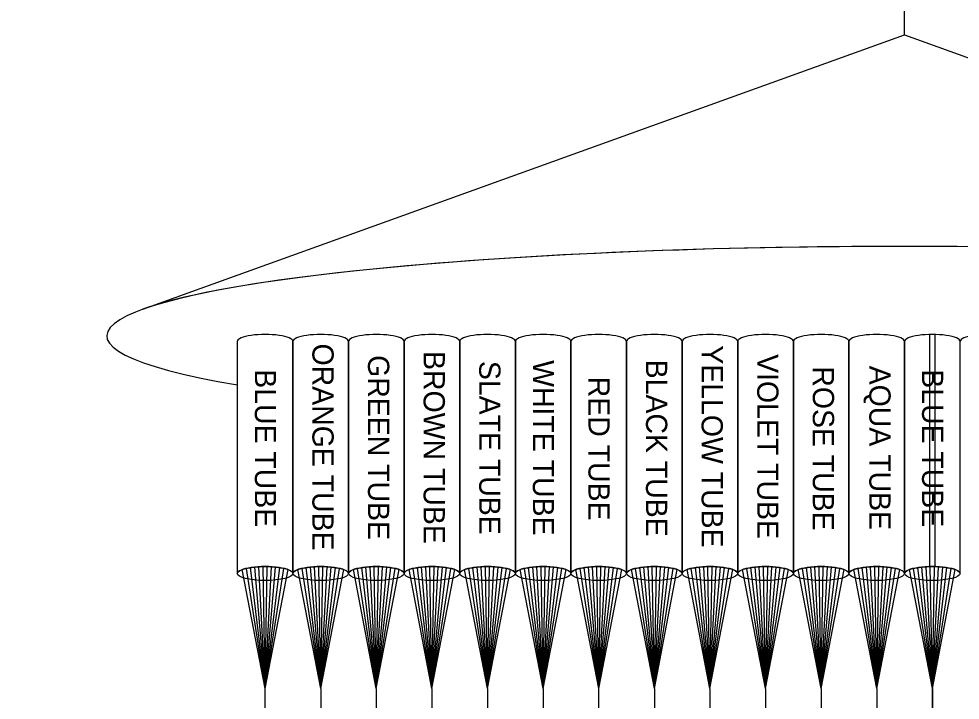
# Model space of a CAD drawing. Extents: x 1805893 to 1833564, y 708898 to 716199.
# Drawn here: x 1831726.3 to 1831827.8, y 715537.7 to 715611.3 of the extents above; entities that cross this region are included whole.
import ezdxf

# ---------------------------------------------------------------- set-up
doc = ezdxf.new("R2010")
doc.units = 0
doc.layers.add('SH_Data', color=7, linetype='Continuous')

msp = doc.modelspace()

# ---------------------------------------------------------------- linework, layer by layer
at = {"layer": 'SH_Data'}
for p, q in [((1831821.84, 715609.51), (1831821.84, 715652.24)), ((1831749.84, 715576.44), (1831749.84, 715551.39)), ((1831749.84, 715576.44), (1831749.84, 715551.39)), ((1831755.84, 715551.39), (1831755.84, 715576.44)), ((1831755.84, 715576.44), (1831755.84, 715551.39)), ((1831761.84, 715576.44), (1831761.84, 715551.39)), ((1831761.84, 715551.39), (1831761.84, 715576.44)), ((1831767.84, 715551.39), (1831767.84, 715576.44)), ((1831767.84, 715576.44), (1831767.84, 715551.39)), ((1831773.84, 715551.39), (1831773.84, 715576.44)), ((1831773.84, 715576.44), (1831773.84, 715551.39)), ((1831779.84, 715551.39), (1831779.84, 715576.44)), ((1831779.84, 715576.44), (1831779.84, 715551.39)), ((1831785.84, 715551.39), (1831785.84, 715576.44)), ((1831785.84, 715576.44), (1831785.84, 715551.39)), ((1831791.84, 715551.39), (1831791.84, 715576.44)), ((1831791.84, 715576.44), (1831791.84, 715551.39)), ((1831797.84, 715576.44), (1831797.84, 715551.39)), ((1831797.84, 715551.39), (1831797.84, 715576.44)), ((1831803.84, 715551.39), (1831803.84, 715576.44)), ((1831803.84, 715576.44), (1831803.84, 715551.39)), ((1831803.84, 715576.44), (1831803.84, 715551.39)), ((1831809.84, 715551.39), (1831809.84, 715576.44)), ((1831809.84, 715576.44), (1831809.84, 715551.39)), ((1831815.84, 715551.39), (1831815.84, 715576.44)), ((1831815.84, 715576.44), (1831815.84, 715551.39)), ((1831821.84, 715551.39), (1831821.84, 715576.44)), ((1831821.84, 715576.44), (1831821.84, 715551.39)), ((1831827.84, 715551.39), (1831827.84, 715576.44)), ((1831752.84, 715538.97), (1831752.17, 715552.12)), ((1831752.84, 715538.97), (1831752.62, 715552.14)), ((1831752.84, 715538.97), (1831753.07, 715552.14)), ((1831752.84, 715538.97), (1831753.52, 715552.12)), ((1831758.84, 715538.97), (1831758.17, 715552.12)), ((1831758.84, 715538.97), (1831758.62, 715552.14)), ((1831758.84, 715538.97), (1831759.07, 715552.14)), ((1831758.84, 715538.97), (1831759.52, 715552.12)), ((1831764.84, 715538.97), (1831764.17, 715552.12)), ((1831764.84, 715538.97), (1831764.62, 715552.14)), ((1831764.84, 715538.97), (1831765.07, 715552.14)), ((1831764.84, 715538.97), (1831765.52, 715552.12)), ((1831770.84, 715538.97), (1831770.17, 715552.12)), ((1831770.84, 715538.97), (1831770.62, 715552.14)), ((1831770.84, 715538.97), (1831771.07, 715552.14)), ((1831770.84, 715538.97), (1831771.52, 715552.12)), ((1831776.84, 715538.97), (1831776.17, 715552.12)), ((1831776.84, 715538.97), (1831776.62, 715552.14)), ((1831776.84, 715538.97), (1831777.07, 715552.14)), ((1831776.84, 715538.97), (1831777.52, 715552.12)), ((1831782.84, 715538.97), (1831782.17, 715552.12)), ((1831782.84, 715538.97), (1831782.62, 715552.14)), ((1831782.84, 715538.97), (1831783.07, 715552.14)), ((1831782.84, 715538.97), (1831783.52, 715552.12)), ((1831788.84, 715538.97), (1831788.17, 715552.12)), ((1831788.84, 715538.97), (1831788.62, 715552.14)), ((1831788.84, 715538.97), (1831789.07, 715552.14)), ((1831788.84, 715538.97), (1831789.52, 715552.12)), ((1831794.84, 715538.97), (1831794.17, 715552.12)), ((1831794.84, 715538.97), (1831794.62, 715552.14)), ((1831794.84, 715538.97), (1831795.07, 715552.14)), ((1831794.84, 715538.97), (1831795.52, 715552.12)), ((1831800.84, 715538.97), (1831800.17, 715552.12)), ((1831800.84, 715538.97), (1831800.62, 715552.14)), ((1831800.84, 715538.97), (1831801.07, 715552.14)), ((1831800.84, 715538.97), (1831801.52, 715552.12)), ((1831806.84, 715538.97), (1831806.17, 715552.12)), ((1831806.84, 715538.97), (1831806.62, 715552.14)), ((1831806.84, 715538.97), (1831807.07, 715552.14)), ((1831806.84, 715538.97), (1831807.52, 715552.12)), ((1831812.84, 715538.97), (1831812.17, 715552.12)), ((1831812.84, 715538.97), (1831812.62, 715552.14)), ((1831812.84, 715538.97), (1831813.07, 715552.14)), ((1831812.84, 715538.97), (1831813.52, 715552.12)), ((1831818.84, 715538.97), (1831818.17, 715552.12)), ((1831818.84, 715538.97), (1831818.62, 715552.14)), ((1831818.84, 715538.97), (1831819.07, 715552.14)), ((1831818.84, 715538.97), (1831819.52, 715552.12)), ((1831824.84, 715538.97), (1831824.17, 715552.12)), ((1831824.84, 715538.97), (1831824.62, 715552.14)), ((1831824.84, 715538.97), (1831825.07, 715552.14)), ((1831824.84, 715538.97), (1831825.52, 715552.12)), ((1831752.84, 715538.97), (1831750.37, 715551.81)), ((1831752.84, 715538.97), (1831750.82, 715551.94)), ((1831752.84, 715538.97), (1831751.27, 715552.03)), ((1831752.84, 715538.97), (1831751.72, 715552.08)), ((1831752.84, 715538.97), (1831753.97, 715552.08)), ((1831752.84, 715538.97), (1831754.42, 715552.03)), ((1831752.84, 715538.97), (1831754.87, 715551.94)), ((1831752.84, 715538.97), (1831755.32, 715551.81)), ((1831758.84, 715538.97), (1831756.37, 715551.81)), ((1831758.84, 715538.97), (1831756.82, 715551.94)), ((1831758.84, 715538.97), (1831757.27, 715552.03)), ((1831758.84, 715538.97), (1831757.72, 715552.08)), ((1831758.84, 715538.97), (1831759.97, 715552.08)), ((1831758.84, 715538.97), (1831760.42, 715552.03)), ((1831758.84, 715538.97), (1831760.87, 715551.94)), ((1831758.84, 715538.97), (1831761.32, 715551.81)), ((1831764.84, 715538.97), (1831762.37, 715551.81)), ((1831764.84, 715538.97), (1831762.82, 715551.94)), ((1831764.84, 715538.97), (1831763.27, 715552.03)), ((1831764.84, 715538.97), (1831763.72, 715552.08)), ((1831764.84, 715538.97), (1831765.97, 715552.08)), ((1831764.84, 715538.97), (1831766.42, 715552.03)), ((1831764.84, 715538.97), (1831766.87, 715551.94)), ((1831764.84, 715538.97), (1831767.32, 715551.81)), ((1831770.84, 715538.97), (1831768.37, 715551.81)), ((1831770.84, 715538.97), (1831768.82, 715551.94)), ((1831770.84, 715538.97), (1831769.27, 715552.03)), ((1831770.84, 715538.97), (1831769.72, 715552.08)), ((1831770.84, 715538.97), (1831771.97, 715552.08)), ((1831770.84, 715538.97), (1831772.42, 715552.03)), ((1831770.84, 715538.97), (1831772.87, 715551.94)), ((1831770.84, 715538.97), (1831773.32, 715551.81)), ((1831776.84, 715538.97), (1831774.37, 715551.81)), ((1831776.84, 715538.97), (1831774.82, 715551.94)), ((1831776.84, 715538.97), (1831775.27, 715552.03)), ((1831776.84, 715538.97), (1831775.72, 715552.08)), ((1831776.84, 715538.97), (1831777.97, 715552.08)), ((1831776.84, 715538.97), (1831778.42, 715552.03)), ((1831776.84, 715538.97), (1831778.87, 715551.94)), ((1831776.84, 715538.97), (1831779.32, 715551.81)), ((1831782.84, 715538.97), (1831780.37, 715551.81)), ((1831782.84, 715538.97), (1831780.82, 715551.94)), ((1831782.84, 715538.97), (1831781.27, 715552.03)), ((1831782.84, 715538.97), (1831781.72, 715552.08)), ((1831782.84, 715538.97), (1831783.97, 715552.08)), ((1831782.84, 715538.97), (1831784.42, 715552.03)), ((1831782.84, 715538.97), (1831784.87, 715551.94)), ((1831782.84, 715538.97), (1831785.32, 715551.81)), ((1831788.84, 715538.97), (1831786.37, 715551.81)), ((1831788.84, 715538.97), (1831786.82, 715551.94)), ((1831788.84, 715538.97), (1831787.27, 715552.03)), ((1831788.84, 715538.97), (1831787.72, 715552.08)), ((1831788.84, 715538.97), (1831789.97, 715552.08)), ((1831788.84, 715538.97), (1831790.42, 715552.03)), ((1831788.84, 715538.97), (1831790.87, 715551.94)), ((1831788.84, 715538.97), (1831791.32, 715551.81)), ((1831794.84, 715538.97), (1831792.37, 715551.81)), ((1831794.84, 715538.97), (1831792.82, 715551.94)), ((1831794.84, 715538.97), (1831793.27, 715552.03)), ((1831794.84, 715538.97), (1831793.72, 715552.08)), ((1831794.84, 715538.97), (1831795.97, 715552.08)), ((1831794.84, 715538.97), (1831796.42, 715552.03)), ((1831794.84, 715538.97), (1831796.87, 715551.94)), ((1831794.84, 715538.97), (1831797.32, 715551.81)), ((1831800.84, 715538.97), (1831798.37, 715551.81)), ((1831800.84, 715538.97), (1831798.82, 715551.94)), ((1831800.84, 715538.97), (1831799.27, 715552.03)), ((1831800.84, 715538.97), (1831799.72, 715552.08)), ((1831800.84, 715538.97), (1831801.97, 715552.08)), ((1831800.84, 715538.97), (1831802.42, 715552.03)), ((1831800.84, 715538.97), (1831802.87, 715551.94)), ((1831800.84, 715538.97), (1831803.32, 715551.81)), ((1831806.84, 715538.97), (1831804.37, 715551.81)), ((1831806.84, 715538.97), (1831804.82, 715551.94)), ((1831806.84, 715538.97), (1831805.27, 715552.03)), ((1831806.84, 715538.97), (1831805.72, 715552.08)), ((1831806.84, 715538.97), (1831807.97, 715552.08)), ((1831806.84, 715538.97), (1831808.42, 715552.03)), ((1831806.84, 715538.97), (1831808.87, 715551.94)), ((1831806.84, 715538.97), (1831809.32, 715551.81)), ((1831812.84, 715538.97), (1831810.37, 715551.81)), ((1831812.84, 715538.97), (1831810.82, 715551.94)), ((1831812.84, 715538.97), (1831811.27, 715552.03)), ((1831812.84, 715538.97), (1831811.72, 715552.08)), ((1831812.84, 715538.97), (1831813.97, 715552.08)), ((1831812.84, 715538.97), (1831814.42, 715552.03)), ((1831812.84, 715538.97), (1831814.87, 715551.94)), ((1831812.84, 715538.97), (1831815.32, 715551.81)), ((1831818.84, 715538.97), (1831816.37, 715551.81)), ((1831818.84, 715538.97), (1831816.82, 715551.94)), ((1831818.84, 715538.97), (1831817.27, 715552.03)), ((1831818.84, 715538.97), (1831817.72, 715552.08)), ((1831818.84, 715538.97), (1831819.97, 715552.08)), ((1831818.84, 715538.97), (1831820.42, 715552.03)), ((1831818.84, 715538.97), (1831820.87, 715551.94)), ((1831818.84, 715538.97), (1831821.32, 715551.81)), ((1831824.84, 715538.97), (1831822.37, 715551.81)), ((1831824.84, 715538.97), (1831822.82, 715551.94)), ((1831824.84, 715538.97), (1831823.27, 715552.03)), ((1831824.84, 715538.97), (1831823.72, 715552.08)), ((1831824.84, 715538.97), (1831825.97, 715552.08)), ((1831824.84, 715538.97), (1831826.42, 715552.03)), ((1831824.84, 715538.97), (1831826.87, 715551.94)), ((1831824.84, 715538.97), (1831827.32, 715551.81)), ((1831752.84, 715504.21), (1831752.84, 715538.97)), ((1831758.84, 715538.97), (1831758.84, 715504.21)), ((1831764.84, 715538.97), (1831764.84, 715504.21)), ((1831770.84, 715538.97), (1831770.84, 715504.21)), ((1831776.84, 715538.97), (1831776.84, 715504.21)), ((1831782.84, 715538.97), (1831782.86, 715504.21)), ((1831788.84, 715504.21), (1831788.84, 715538.97)), ((1831794.84, 715538.97), (1831794.84, 715504.21)), ((1831800.84, 715538.97), (1831800.84, 715504.21)), ((1831806.84, 715538.97), (1831806.84, 715504.21)), ((1831812.84, 715538.97), (1831812.84, 715504.21)), ((1831818.84, 715538.97), (1831818.86, 715504.21)), ((1831824.84, 715538.97), (1831824.84, 715504.21)), ((1831824.84, 715504.21), (1831824.84, 715538.97))]:
    msp.add_line(p, q, dxfattribs=at)
msp.add_lwpolyline([(1831739.65, 715579.92), (1831821.84, 715609.51), (1831904.04, 715579.92)], dxfattribs=at)
msp.add_lwpolyline([(1831739.65, 715579.92), (1831821.84, 715609.51), (1831904.04, 715579.92)], dxfattribs=at)
msp.add_lwpolyline([(1831824.54, 715577.19), (1831824.54, 715552.14), (1831825.14, 715552.14), (1831825.14, 715577.19)], close=True, dxfattribs=at)
for centre, major_axis, ratio, start_param, end_param in [((1831821.84, 715577.04), (86.09, 0), 0.112175, 5.702888, 10.005075), ((1831821.84, 715577.04), (86.09, 0), 0.112175, 5.702888, 10.005075), ((1831821.84, 715577.04), (86.09, 0), 0.112175, 0.302036, 2.839557), ((1831752.84, 715576.44), (3, 0), 0.25, 0, 3.141593), ((1831752.84, 715576.44), (3, 0), 0.25, 0, 3.141593), ((1831758.84, 715576.44), (3, 0), 0.25, 0, 3.141593), ((1831758.84, 715576.44), (3, 0), 0.25, 0, 3.141593), ((1831764.84, 715576.44), (3, 0), 0.25, 0, 3.141593), ((1831764.84, 715576.44), (3, 0), 0.25, 0, 3.141593), ((1831770.84, 715576.44), (3, 0), 0.25, 0, 3.141593), ((1831770.84, 715576.44), (3, 0), 0.25, 0, 3.141593), ((1831776.84, 715576.44), (3, 0), 0.25, 0, 3.141593), ((1831776.84, 715576.44), (3, 0), 0.25, 0, 3.141593), ((1831782.84, 715576.44), (3, 0), 0.25, 0, 3.141593), ((1831782.84, 715576.44), (3, 0), 0.25, 0, 3.141593), ((1831788.84, 715576.44), (3, 0), 0.25, 0, 3.141593), ((1831788.84, 715576.44), (3, 0), 0.25, 0, 3.141593), ((1831794.84, 715576.44), (3, 0), 0.25, 0, 3.141593), ((1831794.84, 715576.44), (3, 0), 0.25, 0, 3.141593), ((1831800.84, 715576.44), (3, 0), 0.25, 0, 3.141593), ((1831800.84, 715576.44), (3, 0), 0.25, 0, 3.141593), ((1831806.84, 715576.44), (3, 0), 0.25, 0, 3.141593), ((1831806.84, 715576.44), (3, 0), 0.25, 0, 3.141593), ((1831812.84, 715576.44), (3, 0), 0.25, 0, 3.141593), ((1831812.84, 715576.44), (3, 0), 0.25, 0, 3.141593), ((1831818.84, 715576.44), (3, 0), 0.25, 0, 3.141593), ((1831818.84, 715576.44), (3, 0), 0.25, 0, 3.141593), ((1831824.84, 715576.44), (3, 0), 0.25, 0, 3.141593), ((1831824.84, 715576.44), (3, 0), 0.25, 0, 3.141593), ((1831830.84, 715576.44), (3, 0), 0.25, 0, 3.141593), ((1831752.84, 715551.39), (3, 0), 0.25, 0, 3.141593), ((1831758.84, 715551.39), (3, 0), 0.25, 0, 3.141593), ((1831764.84, 715551.39), (3, 0), 0.25, 0, 3.141593), ((1831770.84, 715551.39), (3, 0), 0.25, 0, 3.141593), ((1831776.84, 715551.39), (3, 0), 0.25, 0, 3.141593), ((1831782.84, 715551.39), (3, 0), 0.25, 0, 3.141593), ((1831788.84, 715551.39), (3, 0), 0.25, 0, 3.141593), ((1831794.84, 715551.39), (3, 0), 0.25, 0, 3.141593), ((1831800.84, 715551.39), (3, 0), 0.25, 0, 3.141593), ((1831806.84, 715551.39), (3, 0), 0.25, 0, 3.141593), ((1831812.84, 715551.39), (3, 0), 0.25, 0, 3.141593), ((1831818.84, 715551.39), (3, 0), 0.25, 0, 3.141593), ((1831824.84, 715551.39), (3, 0), 0.25, 0, 3.141593)]:
    msp.add_ellipse(centre, major_axis=major_axis, ratio=ratio, start_param=start_param, end_param=end_param, dxfattribs=at)
for centre in [(1831752.84, 715551.39), (1831758.84, 715551.39), (1831764.84, 715551.39), (1831770.84, 715551.39), (1831776.84, 715551.39), (1831782.84, 715551.39), (1831788.84, 715551.39), (1831794.84, 715551.39), (1831800.84, 715551.39), (1831806.84, 715551.39), (1831812.84, 715551.39), (1831818.84, 715551.39), (1831824.84, 715551.39)]:
    msp.add_ellipse(centre, major_axis=(3, 0), ratio=0.25, dxfattribs=at)

# ---------------------------------------------------------------- texts
for s, height, p in [('ORANGE TUBE', 2.2947, (1831757.94, 715576.21)), ('YELLOW TUBE', 2.2947, (1831799.94, 715576.02)), ('GREEN TUBE', 2.295, (1831763.94, 715574.96)), ('BROWN TUBE', 2.295, (1831769.94, 715575.4)), ('VIOLET TUBE', 2.2947, (1831805.94, 715575.07)), ('SLATE TUBE', 2.295, (1831775.94, 715574.34)), ('WHITE TUBE', 2.295, (1831781.73, 715574.42)), ('BLACK TUBE', 2.295, (1831793.94, 715574.47)), ('ROSE TUBE', 2.295, (1831811.94, 715573.75)), ('AQUA TUBE', 2.295, (1831818.04, 715573.82)), ('BLUE TUBE', 2.295, (1831751.73, 715573.44)), ('BLUE TUBE', 2.295, (1831823.73, 715573.44)), ('RED TUBE', 2.295, (1831787.73, 715572.63))]:
    msp.add_text(s, height=height, rotation=270, dxfattribs=at).set_placement(p)

doc.saveas('drawing.dxf')
